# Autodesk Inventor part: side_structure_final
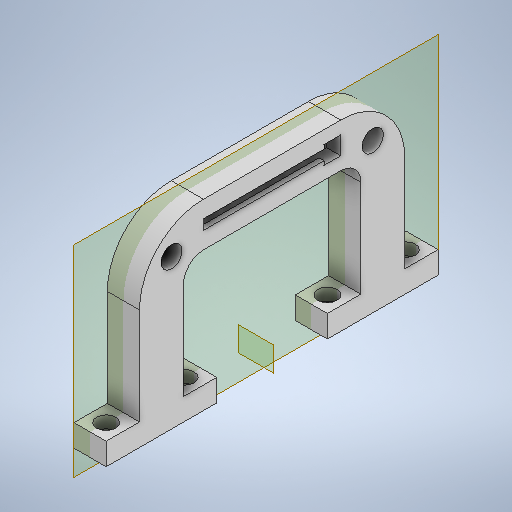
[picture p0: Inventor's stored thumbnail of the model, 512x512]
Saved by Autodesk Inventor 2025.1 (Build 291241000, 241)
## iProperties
Created: 2024-10
Part Number: side_structure_final
Material: Generic
Document SubType Name: Modeling
Designer: mansa
Density: 1 g/cm^3
Appearance: Default
Author: mansa
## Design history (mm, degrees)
sketch "Sketch1"
  geometry: L1 (0, 0)-(16, 0); L2 (16, 0)-(16, 55); L3 (16, 55)-(0, 55); L4 (0, 55)-(0, 0)
  constraints: 8 end point, 2 parallel, 1 horizontal, 1 perpendicular
  dimensions: "d0" = 55 distance between parallel lines of L3 L1; "d15" = 16 distance of L2.end L3.end
extrude "Extrusion1" new body sketch "Sketch1" distance "d1" = 11; taper "d2" = 0 deg
sketch "Sketch2"
  geometry: L1 (-16, 0)-(-16, -55) reference; L2 (-16, -27.5)-(0, -27.5); L3 (-16, -55)-(0, -55) reference; L4 (-8, -55)-(-8, 0); 3 further points
  constraints: 4 end point, 2 midpoint, 1 horizontal, 1 point on line, 1 symmetric about line, 1 vertical
  dimensions: "d6" = 8 distance from line of L3 point (-8, -47)
hole "Hole1" sketch "Sketch2" at (-8, -47), (-8, -8) diameter "d8" = 5.8; stored, may be unused: countersink angle "d12" = 82 deg, drill point angle "d14" = 118 deg; dims "d9" = 6, "d10" = 9.5, "d11" = 6, "d13" = 8
sketch "Sketch3"
  geometry: L1 (-16, 0)-(-16, -55) reference; L2 (-16, -27.5)-(0, -27.5); L3 (0, 0)-(-16, 0) reference; L4 (-8, 0)-(-8, -55); L5 (-16, -55)-(0, -55) reference; L6 (0, -55)-(0, 0) reference; L7 (-16, -38.4)-(0, -38.4); L8 (0, -38.4)-(0, -16.6); L9 (0, -16.6)-(-16, -16.6); L10 (-16, -16.6)-(-16, -38.4); L11 (-16, -42.25)-(0, -42.25); L12 (-16, -12.75)-(0, -12.75); C1 r 4.75 at (-8, -47) reference; C2 r 4.75 at (-8, -8) reference
  constraints: 16 end point, 6 point on line, 3 midpoint, 3 perpendicular, 2 horizontal, 2 parallel, 2 tangent
  dimensions: "d46" = 21.8 diameter of L7 L2; "d47" = 21.8 diameter of L9 L2
extrude "Extrusion2" join sketch "Sketch3" distance "d19" = 80; taper "d20" = 0 deg
workplane "Work Plane1"
mirror "Mirror1"
sketch "Sketch4"
  geometry: L1 (16, 80)-(0, 80) reference; L2 (0, 0)-(0, 80) reference; L3 (16, 0)-(16, 80) reference; L4 (0, 80)-(16, 80); L5 (16, 80)-(16, 58.2); L6 (16, 58.2)-(0, 58.2); L7 (0, 58.2)-(0, 80); 1 further point
  constraints: 8 end point, 2 parallel, 1 horizontal, 1 perpendicular, 1 point on line
  dimensions: "d22" = 21.8 distance between parallel lines of L1 L6
extrude "Extrusion3" join sketch "Sketch4" stored distance "d23" = 80; taper "d24" = 0 deg
fillet "Fillet5" dims "d31" = 10
fillet "Fillet6" dims "d32" = 31.8
mirror "Mirror3"
sketch "Sketch6"
  geometry: 1 further point
sketch "Sketch7"
  geometry: L1 (6.6, 91)-(-61.6, 91) reference; L2 (-27.5, 91)-(-27.5, 69.2); L3 (6.6, 69.2)-(-61.6, 69.2) reference; C1 r 5.25 at (-77.5, 74.2); C2 r 5.25 at (22.5, 74.2); 3 further points
  constraints: 2 centre point, 2 coincident, 2 end point, 2 midpoint, 1 symmetric about line
  dimensions: "d33" = 100 diameter of point (-77.5, 74.2) L2; "d34" = 5 distance from line of L3 point (-77.5, 74.2); "d35" = 10.5 diameter of C1; "d36" = 10.5 diameter of C2
extrude "Extrusion4" cut sketch "Sketch7" distance "d37" = 16; taper "d38" = 0 deg
sketch "Sketch8"
  geometry: L1 (48.4, 91)-(116.6, 91) reference; L2 (48.4, 69.2)-(116.6, 69.2) reference; L3 (48.4, 84.6)-(116.6, 84.6); L4 (116.6, 84.6)-(116.6, 75.6); L5 (116.6, 75.6)-(48.4, 75.6); L6 (48.4, 75.6)-(48.4, 84.6); L7 (48.4, 91)-(48.4, 69.2); L8 (116.6, 91)-(116.6, 69.2); L9 (48.4, 80.1)-(116.6, 80.1); A1 r 31.8 centre (48.4, 59.2) between (48.4, 91) and (16.6, 59.2) reference; 1 further point
  constraints: 14 end point, 3 parallel, 2 collinear, 2 midpoint, 1 horizontal, 1 perpendicular, 1 vertical, 1 other
  dimensions: "d39" = 9 distance between parallel lines of L5 L3
extrude "Extrusion5" cut sketch "Sketch8" distance "d40" = 7; taper "d41" = 0 deg
sketch "Sketch9"
  geometry: L1 (0, 0)-(0, 9) reference; L2 (0, 0)-(7, 0) reference; L3 (0, 2)-(2.5, 2); L4 (2.5, 2)-(2.5, 0); L5 (2.5, 0)-(0, 0); L6 (0, 0)-(0, 2); 1 further point
  constraints: 8 end point, 2 parallel, 2 point on line, 1 horizontal, 1 perpendicular
  dimensions: "d42" = 2 distance of L3.end L4.end; "d43" = 2.5 distance of L3.start L3.end
extrude "Extrusion6" join sketch "Sketch9" distance "d44" = 59.95; taper "d45" = 0 deg
workplane "Work Plane2"
mirror "Mirror4"
workplane "Work Plane3"
body "Solid1"
other parameters: "d21" = 27.5
